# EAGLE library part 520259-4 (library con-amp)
AMP connector
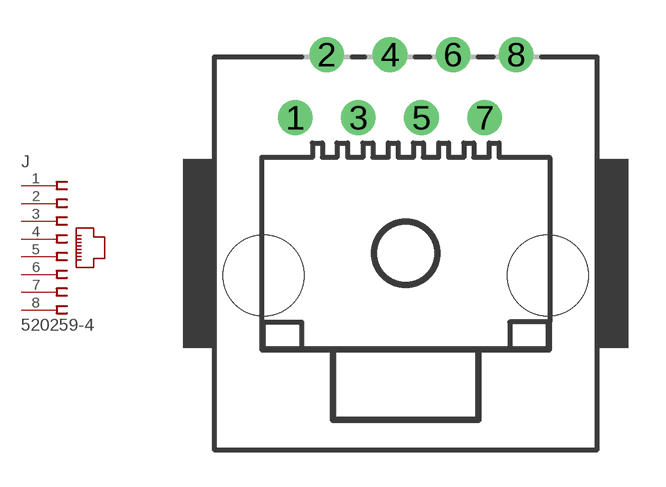
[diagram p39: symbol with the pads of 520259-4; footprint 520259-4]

Designator prefix J

## 520259-4 (MF: TYCO ELECTRONICS; MPN: 5520259-4; OC_FARNELL: 1214653; OC_NEWARK: 42K7228)  [520259-4]
1  1  pas
2  2  pas
3  3  pas
4  4  pas
5  5  pas
6  6  pas
7  7  pas
8  8  pas

## Footprint 520259-4 (pad centres in mm)
Modular Jack with Panel Stops
drill 0.889 round: 1 -4.445,5.461; 2 -3.175,8.001; 3 -1.905,5.461; 4 -0.635,8.001; 5 0.635,5.461; 6 1.905,8.001; 7 3.175,5.461; 8 4.445,8.001
hole 3.251 at -5.715,-0.889
hole 3.251 at 5.715,-0.889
